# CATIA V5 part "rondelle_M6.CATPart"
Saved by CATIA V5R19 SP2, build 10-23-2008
Part number: FR_10019 (M6 Washer)
Publications: "FaceSup", "FaceInf", "AxeVis"
Material "Steel": density 7860 kg/m3, Young's modulus 2e+11 Pa, Poisson ratio 0.266, thermal expansion 1.17e-05 1/K
Bounding box of the stored display mesh (mm): x -6 to 6, y -5.85 to 5.85, z 0 to 1.6
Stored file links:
  C:\Users\axelc\Desktop\EPSA\ELIZ-2021\Insertion_visserie\visserie\MacroInsertion\catalogue_visserie_outils\Rondelle\Standard\rondelle_M6.CATPart
  C:\Users\Brice\Documents\cours_centrale\S8\maquette numérique\Vis parametrique\parametreRondelle.xls
  C:\Users\Brice\Documents\cours_centrale\S8\maquette numérique\Vis parametrique\VisEcrou.CATProduct
  C:\Users\arthu\OneDrive\Documents\EPSA\Optipute\SU - Suspension\00 - Matériaux\Catalog.CATMaterial
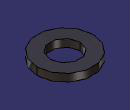
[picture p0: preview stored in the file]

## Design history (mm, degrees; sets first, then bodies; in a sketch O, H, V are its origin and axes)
Parameters
  diametre_interieur = 6.4 mm
  diametre_exterieur = 12 mm
  epaisseur = 1.6 mm
Body1 (main body)
  Sketch1 on xy-plane, origin (0, 0, 0), H (1, 0, 0), V (0, 1, 0)
    circle A1 centre (0, 0) radius 3.2
    circle A2 centre (0, 0) radius 6
    radius A1 = 3.2 {= diametre_interieur /2}
    radius A2 = 6 {= diametre_exterieur /2}
    concentricity: A1 O, A2 A1
  Pad1: profile Sketch1, direction (0, 0, 1), length 1.6 {= epaisseur}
